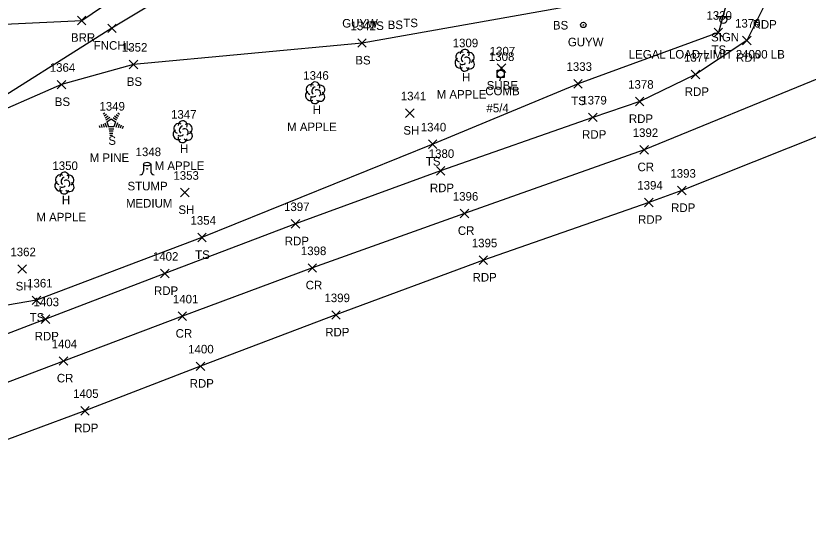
# Model space of a CAD drawing. Extents: x 1688195 to 1692013, y 424605 to 441234.
# Drawn here: x 1691718.1 to 1691903, y 439041.4 to 439158.5 of the extents above; entities that cross this region are included whole.
import ezdxf

# ---------------------------------------------------------------- set-up
doc = ezdxf.new("R2010")
doc.units = 0
for name, color, linetype in [('L_A', 7, 'Continuous'), ('L_C', 7, 'Continuous'), ('L_I', 7, 'Continuous'), ('L_TIC', 7, 'Continuous'), ('LABL', 7, 'Continuous'), ('LELB', 7, 'Continuous'), ('LFNC', 7, 'Continuous'), ('LTC', 7, 'Continuous'), ('LTD', 7, 'Continuous'), ('LTS', 7, 'Continuous'), ('P_A', 7, 'Continuous'), ('P_I', 7, 'Continuous'), ('P_TIC', 7, 'Continuous'), ('PET', 7, 'Continuous'), ('PRC', 7, 'Continuous'), ('S_A', 7, 'Continuous'), ('S_C', 7, 'Continuous'), ('SSGN', 7, 'Continuous'), ('U_A', 7, 'Continuous'), ('U_C', 7, 'Continuous'), ('U_I', 7, 'Continuous'), ('U_TIC', 7, 'Continuous'), ('UP', 7, 'Continuous'), ('UPGW', 7, 'Continuous')]:
    doc.layers.add(name, color=color, linetype=linetype)

msp = doc.modelspace()

# ---------------------------------------------------------------- linework, layer by layer
at = {"layer": 'L_TIC'}
for points in [[(1691732.43, 439156.4), (1691734.43, 439158.4)], [(1691734.43, 439156.4), (1691732.43, 439158.4)], [(1691739.49, 439154.55), (1691741.49, 439156.55)], [(1691741.49, 439154.55), (1691739.49, 439156.55)], [(1691881, 439153.55), (1691883, 439155.55)], [(1691883, 439153.55), (1691881, 439155.55)], [(1691797.84, 439151.11), (1691799.84, 439153.11)], [(1691799.84, 439151.11), (1691797.84, 439153.11)], [(1691744.51, 439146.11), (1691746.51, 439148.11)], [(1691746.51, 439146.11), (1691744.51, 439148.11)], [(1691727.71, 439141.4), (1691729.71, 439143.4)], [(1691729.71, 439141.4), (1691727.71, 439143.4)], [(1691848.25, 439141.61), (1691850.25, 439143.61)], [(1691850.25, 439141.61), (1691848.25, 439143.61)], [(1691809.01, 439134.72), (1691811.01, 439136.72)], [(1691811.01, 439134.72), (1691809.01, 439136.72)], [(1691814.33, 439127.47), (1691816.33, 439129.47)], [(1691816.33, 439127.47), (1691814.33, 439129.47)], [(1691756.51, 439116.18), (1691758.51, 439118.18)], [(1691758.51, 439116.18), (1691756.51, 439118.18)], [(1691760.5, 439105.68), (1691762.5, 439107.68)], [(1691762.5, 439105.68), (1691760.5, 439107.68)], [(1691718.52, 439098.33), (1691720.52, 439100.33)], [(1691720.52, 439098.33), (1691718.52, 439100.33)], [(1691721.87, 439091.03), (1691723.87, 439093.03)], [(1691723.87, 439091.03), (1691721.87, 439093.03)]]:
    msp.add_lwpolyline(points, dxfattribs=at)
at = {"layer": 'LABL'}
msp.add_lwpolyline([(1691601.59, 439075.8), (1691600.49, 439085.06), (1691627.74, 439119.17), (1691640.71, 439127.56), (1691655.14, 439108.61), (1691685.11, 439134.92), (1691687.62, 439141.73), (1691698.9, 439155.76), (1691733.43, 439157.4), (1691776.41, 439186.57), (1691794.38, 439190.21)], dxfattribs=at)
at = {"layer": 'LELB'}
for points in [[(1691809.05, 439198.7), (1691810.07, 439220.42), (1691810.47, 439227.71), (1691810.04, 439233.75), (1691820.98, 439231.16), (1691837.25, 439226.41), (1691844.55, 439222.68), (1691860.67, 439213.28), (1691879.41, 439197.19), (1691884.86, 439187.77), (1691888.44, 439178.13), (1691882, 439154.55), (1691849.25, 439142.61), (1691815.33, 439128.47), (1691761.5, 439106.68), (1691722.87, 439092.03), (1691697.52, 439087.73), (1691657.95, 439070.39), (1691613.62, 439049.58), (1691576.98, 439020.14), (1691544.83, 438993.15), (1691508.2, 438954.88), (1691488.69, 438935.2)], [(1691867.08, 439165.21), (1691844.95, 439160.27), (1691798.84, 439152.11), (1691745.51, 439147.11), (1691728.71, 439142.4), (1691709.09, 439133.88), (1691683, 439117.2), (1691643.28, 439091.08), (1691604.89, 439061.29), (1691572.53, 439026.72), (1691542.38, 438995.55), (1691505.84, 438957.5), (1691487.66, 438936.34), (1691466.81, 438915.54), (1691436.02, 438880.86), (1691415.55, 438858.76)]]:
    msp.add_lwpolyline(points, dxfattribs=at)
at = {"layer": 'LFNC'}
msp.add_lwpolyline([(1691844.63, 439219.19), (1691827.3, 439208.18), (1691808.98, 439197.07), (1691805.18, 439194.78), (1691802.65, 439193.15), (1691780.93, 439179.95), (1691740.49, 439155.55), (1691707.63, 439134.9), (1691682.09, 439120.04), (1691638.96, 439093.47), (1691599.84, 439067.34), (1691566.38, 439033.38), (1691536.95, 439001.22), (1691500.89, 438961.26), (1691462.91, 438919.55), (1691429.39, 438883.14), (1691411.26, 438863.12)], dxfattribs=at)
at = {"layer": 'LTC'}
for p, q in [((1691738.46, 439135.55), (1691738.82, 439135.81)), ((1691738.67, 439135.09), (1691739.2, 439135.47)), ((1691738.88, 439134.62), (1691739.58, 439135.13)), ((1691739.09, 439134.15), (1691739.97, 439134.79)), ((1691740.75, 439134.75), (1691741.56, 439134.16)), ((1691741.12, 439135.09), (1691741.8, 439134.6)), ((1691741.49, 439135.44), (1691742.04, 439135.04)), ((1691741.86, 439135.79), (1691742.28, 439135.49)), ((1691737.49, 439132.83), (1691737.65, 439132.36)), ((1691737.95, 439133.05), (1691738.16, 439132.39)), ((1691738.4, 439133.26), (1691738.68, 439132.43)), ((1691738.86, 439133.48), (1691739.19, 439132.46)), ((1691739.31, 439133.7), (1691740.33, 439134.43)), ((1691739.31, 439133.7), (1691739.7, 439132.51)), ((1691740.33, 439134.43), (1691741.32, 439133.71)), ((1691741.32, 439133.71), (1691740.93, 439132.51)), ((1691741.76, 439133.44), (1691741.42, 439132.4)), ((1691742.2, 439133.19), (1691741.92, 439132.3)), ((1691742.65, 439132.94), (1691742.41, 439132.21)), ((1691740.93, 439132.51), (1691739.7, 439132.51)), ((1691740.89, 439132.01), (1691739.75, 439132.01)), ((1691740.81, 439131.51), (1691739.82, 439131.51)), ((1691740.73, 439131.01), (1691739.89, 439131.01)), ((1691743.09, 439132.69), (1691742.91, 439132.11)), ((1691740.64, 439130.51), (1691739.97, 439130.51))]:
    msp.add_line(p, q, dxfattribs=at)
at = {"layer": 'LTD'}
for p, q in [((1691822.78, 439148.13), (1691822.78, 439148.13)), ((1691822.78, 439148.13), (1691822.78, 439148.13)), ((1691787.88, 439140.54), (1691787.88, 439140.54)), ((1691787.88, 439140.54), (1691787.88, 439140.54)), ((1691756.97, 439131.45), (1691756.97, 439131.45)), ((1691756.97, 439131.45), (1691756.97, 439131.45)), ((1691729.37, 439119.46), (1691729.37, 439119.46)), ((1691729.37, 439119.46), (1691729.37, 439119.46))]:
    msp.add_line(p, q, dxfattribs=at)
for centre in [(1691822.82, 439149.57), (1691787.93, 439141.97), (1691757.02, 439132.88), (1691729.41, 439120.9)]:
    msp.add_arc(centre, 1.05, 335.5272, 180.9563, dxfattribs=at)
for centre, major_axis, ratio, start_param, end_param in [((1691821.99, 439148.8), (1.21, -0.51), 0.895232, 1.570796, 4.712389), ((1691822.57, 439148.59), (-0.208, -0.792), 0.645439, 3.141593, 6.283185), ((1691823.82, 439148.72), (-1.14, -0.48), 0.949671, 1.570796, 4.712389), ((1691821.69, 439147.43), (0.58, -1.04), 0.959034, 3.141593, 6.283185), ((1691823.28, 439147.97), (-0.5, 0.667), 0.989748, 3.141593, 6.283185), ((1691823.78, 439147.3), (-1.09, 0.79), 0.841452, 1.570796, 4.712389), ((1691822.78, 439146.63), (0.26, 1.06), 0.942809, 1.570796, 4.712389), ((1691822.32, 439147.38), (-0.625, -0.083), 0.423636, 0, 3.141593), ((1691787.09, 439141.21), (1.21, -0.51), 0.895232, 1.570796, 4.712389), ((1691788.92, 439141.12), (-1.14, -0.48), 0.949671, 1.570796, 4.712389), ((1691786.8, 439139.83), (0.58, -1.04), 0.959034, 3.141593, 6.283185), ((1691787.67, 439141), (-0.208, -0.792), 0.645439, 3.141593, 6.283185), ((1691788.38, 439140.37), (-0.5, 0.667), 0.989748, 3.141593, 6.283185), ((1691788.88, 439139.71), (-1.09, 0.79), 0.841452, 1.570796, 4.712389), ((1691787.88, 439139.04), (0.26, 1.06), 0.942809, 1.570796, 4.712389), ((1691787.42, 439139.79), (-0.625, -0.083), 0.423636, 0, 3.141593), ((1691756.18, 439132.11), (1.21, -0.51), 0.895232, 1.570796, 4.712389), ((1691756.76, 439131.91), (-0.208, -0.792), 0.645439, 3.141593, 6.283185), ((1691758.01, 439132.03), (-1.14, -0.48), 0.949671, 1.570796, 4.712389), ((1691755.89, 439130.74), (0.58, -1.04), 0.959034, 3.141593, 6.283185), ((1691757.47, 439131.28), (-0.5, 0.667), 0.989748, 3.141593, 6.283185), ((1691757.97, 439130.62), (-1.09, 0.79), 0.841452, 1.570796, 4.712389), ((1691756.97, 439129.95), (0.26, 1.06), 0.942809, 1.570796, 4.712389), ((1691756.51, 439130.7), (-0.625, -0.083), 0.423636, 0, 3.141593), ((1691728.57, 439120.13), (1.21, -0.51), 0.895232, 1.570796, 4.712389), ((1691729.16, 439119.92), (-0.208, -0.792), 0.645439, 3.141593, 6.283185), ((1691729.87, 439119.3), (-0.5, 0.667), 0.989748, 3.141593, 6.283185), ((1691730.41, 439120.05), (-1.14, -0.48), 0.949671, 1.570796, 4.712389), ((1691728.28, 439118.75), (0.58, -1.04), 0.959034, 3.141593, 6.283185), ((1691729.37, 439117.96), (0.26, 1.06), 0.942809, 1.570796, 4.712389), ((1691728.91, 439118.71), (-0.625, -0.083), 0.423636, 0, 3.141593), ((1691730.37, 439118.63), (-1.09, 0.79), 0.841452, 1.570796, 4.712389)]:
    msp.add_ellipse(centre, major_axis=major_axis, ratio=ratio, start_param=start_param, end_param=end_param, dxfattribs=at)
at = {"layer": 'LTS'}
for p, q in [((1691747.86, 439123.84), (1691747.86, 439122.18)), ((1691749.53, 439123.68), (1691749.53, 439123.84)), ((1691749.53, 439123.84), (1691749.53, 439122.18)), ((1691748.69, 439122.7), (1691748.69, 439122.7)), ((1691748.69, 439122.7), (1691748.69, 439122.7)), ((1691748.69, 439122.68), (1691748.69, 439122.68))]:
    msp.add_line(p, q, dxfattribs=at)
msp.add_circle((1691748.69, 439122.7), 0.0833, dxfattribs=at)
for centre, start, end in [((1691747.03, 439122.18), 270, 360), ((1691750.36, 439122.18), 180, 270)]:
    msp.add_arc(centre, 0.833, start, end, dxfattribs=at)
msp.add_ellipse((1691748.69, 439123.84), major_axis=(-0.833, 0), ratio=0.5, dxfattribs=at)
at = {"layer": 'P_TIC'}
for points in [[(1691887.63, 439151.73), (1691889.63, 439153.73)], [(1691889.63, 439151.73), (1691887.63, 439153.73)], [(1691875.67, 439143.76), (1691877.67, 439145.76)], [(1691877.67, 439143.76), (1691875.67, 439145.76)], [(1691862.64, 439137.44), (1691864.64, 439139.44)], [(1691864.64, 439137.44), (1691862.64, 439139.44)], [(1691851.71, 439133.76), (1691853.71, 439135.76)], [(1691853.71, 439133.76), (1691851.71, 439135.76)], [(1691863.7, 439126.18), (1691865.7, 439128.18)], [(1691865.7, 439126.18), (1691863.7, 439128.18)], [(1691816.19, 439121.28), (1691818.19, 439123.28)], [(1691818.19, 439121.28), (1691816.19, 439123.28)], [(1691872.49, 439116.66), (1691874.49, 439118.66)], [(1691874.49, 439116.66), (1691872.49, 439118.66)], [(1691864.77, 439113.89), (1691866.77, 439115.89)], [(1691866.77, 439113.89), (1691864.77, 439115.89)], [(1691821.78, 439111.3), (1691823.78, 439113.3)], [(1691823.78, 439111.3), (1691821.78, 439113.3)], [(1691782.33, 439108.87), (1691784.33, 439110.87)], [(1691784.33, 439108.87), (1691782.33, 439110.87)], [(1691826.16, 439100.41), (1691828.16, 439102.41)], [(1691828.16, 439100.41), (1691826.16, 439102.41)], [(1691786.26, 439098.58), (1691788.26, 439100.58)], [(1691788.26, 439098.58), (1691786.26, 439100.58)], [(1691751.81, 439097.27), (1691753.81, 439099.27)], [(1691753.81, 439097.27), (1691751.81, 439099.27)], [(1691723.96, 439086.65), (1691725.96, 439088.65)], [(1691725.96, 439086.65), (1691723.96, 439088.65)], [(1691755.92, 439087.3), (1691757.92, 439089.3)], [(1691757.92, 439087.3), (1691755.92, 439089.3)], [(1691791.77, 439087.6), (1691793.77, 439089.6)], [(1691793.77, 439087.6), (1691791.77, 439089.6)], [(1691728.19, 439076.85), (1691730.19, 439078.85)], [(1691730.19, 439076.85), (1691728.19, 439078.85)], [(1691760.14, 439075.62), (1691762.14, 439077.62)], [(1691762.14, 439075.62), (1691760.14, 439077.62)], [(1691733.19, 439065.23), (1691735.19, 439067.23)], [(1691735.19, 439065.23), (1691733.19, 439067.23)]]:
    msp.add_lwpolyline(points, dxfattribs=at)
at = {"layer": 'PET'}
for points in [[(1691892.5, 439160.46), (1691888.63, 439152.73), (1691876.67, 439144.76), (1691863.64, 439138.44), (1691852.71, 439134.76), (1691817.19, 439122.28), (1691783.33, 439109.87), (1691752.81, 439098.27), (1691724.96, 439087.65), (1691700.6, 439078.32)], [(1691962.88, 439130.56), (1691955.64, 439134.26), (1691948.02, 439136.72), (1691941.11, 439138.03), (1691934.22, 439138.24), (1691927.22, 439137.24), (1691921.33, 439135.77), (1691915.1, 439134.27), (1691873.49, 439117.66), (1691865.77, 439114.89), (1691827.16, 439101.41), (1691792.77, 439088.6), (1691761.14, 439076.62), (1691734.19, 439066.23), (1691708.14, 439056.57), (1691672.86, 439042.9), (1691649.54, 439032.89)]]:
    msp.add_lwpolyline(points, dxfattribs=at)
at = {"layer": 'PRC'}
msp.add_lwpolyline([(1691888.13, 439193.66), (1691921.53, 439164.99), (1691933.61, 439155.1), (1691905.33, 439143.8), (1691864.7, 439127.18), (1691822.78, 439112.3), (1691787.26, 439099.58), (1691756.92, 439088.3), (1691729.19, 439077.85), (1691704.03, 439068.3), (1691667.7, 439053.5), (1691645.71, 439043.49), (1691628.46, 439034.88), (1691608.73, 439022.92), (1691585.22, 439006.39), (1691574.92, 438998.75), (1691559.84, 438985.93), (1691543.5, 438970.76), (1691518.61, 438946.02), (1691478.27, 438903.21), (1691447.81, 438870), (1691426.94, 438847.45)], dxfattribs=at)
at = {"layer": 'SSGN'}
for p, q in [((1691881.51, 439158.34), (1691884.85, 439158.34)), ((1691883.16, 439157.51), (1691883.16, 439157.51))]:
    msp.add_line(p, q, dxfattribs=at)
msp.add_circle((1691883.16, 439157.51), 0.833, dxfattribs=at)
at = {"layer": 'U_TIC'}
for points in [[(1691830.4, 439145.22), (1691832.4, 439147.22)], [(1691832.4, 439145.22), (1691830.4, 439147.22)]]:
    msp.add_lwpolyline(points, dxfattribs=at)
at = {"layer": 'UP'}
for p, q in [((1691830.38, 439144.08), (1691830.38, 439145.75)), ((1691830.38, 439145.75), (1691832.05, 439145.75)), ((1691831.47, 439146.58), (1691831.22, 439145.75)), ((1691832.05, 439145.75), (1691832.05, 439144.08)), ((1691832.05, 439144.08), (1691830.38, 439144.08)), ((1691830.97, 439143.25), (1691831.22, 439144.08)), ((1691831.22, 439144.92), (1691831.22, 439144.92))]:
    msp.add_line(p, q, dxfattribs=at)
msp.add_circle((1691831.22, 439144.92), 0.833, dxfattribs=at)
at = {"layer": 'UPGW'}
for radius in [0.625, 0.0833]:
    msp.add_circle((1691850.49, 439156.34), radius, dxfattribs=at)

# ---------------------------------------------------------------- texts
at = {"layer": 'L_A'}
for s, p in [('TS', (1691800.52, 439155.16)), ('BS', (1691804.83, 439155.37)), ('TS', (1691808.48, 439155.82)), ('BS', (1691843.39, 439155.27)), ('BRR', (1691730.92, 439152.4)), ('FNCHL', (1691736.24, 439150.55)), ('TS', (1691880.41, 439149.55)), ('BS', (1691797.28, 439147.11)), ('BS', (1691743.95, 439142.11)), ('H', (1691822.21, 439143.13)), ('BS', (1691727.15, 439137.4)), ('TS', (1691847.66, 439137.61)), ('H', (1691787.32, 439135.54)), ('SH', (1691808.5, 439130.72)), ('S', (1691739.65, 439128.34)), ('H', (1691756.4, 439126.45)), ('TS', (1691813.73, 439123.47)), ('STUMP', (1691744.12, 439117.7)), ('H', (1691728.8, 439114.46)), ('SH', (1691756, 439112.18)), ('TS', (1691759.91, 439101.68)), ('SH', (1691718.01, 439094.33)), ('TS', (1691721.28, 439087.03))]:
    msp.add_text(s, height=2, dxfattribs=at).set_placement(p)
at = {"layer": 'L_C'}
for s, p in [('M APPLE', (1691816.26, 439139.13)), ('M APPLE', (1691781.36, 439131.54)), ('M PINE', (1691735.29, 439124.34)), ('M APPLE', (1691750.45, 439122.45)), ('MEDIUM', (1691743.75, 439113.7)), ('M APPLE', (1691722.85, 439110.46))]:
    msp.add_text(s, height=2, dxfattribs=at).set_placement(p)
at = {"layer": 'L_I'}
for s, p in [('1330', (1691879.22, 439157.55)), ('1342', (1691796.14, 439155.11)), ('1309', (1691820, 439151.13)), ('1352', (1691742.81, 439150.11)), ('1333', (1691846.56, 439145.61)), ('1364', (1691725.97, 439145.4)), ('1346', (1691785.13, 439143.54)), ('1341', (1691807.89, 439138.72)), ('1349', (1691737.56, 439136.34)), ('1347', (1691754.28, 439134.45)), ('1340', (1691812.55, 439131.47)), ('1348', (1691746, 439125.7)), ('1350', (1691726.59, 439122.46)), ('1353', (1691754.82, 439120.18)), ('1354', (1691758.81, 439109.68)), ('1362', (1691716.78, 439102.33)), ('1361', (1691720.69, 439095.03))]:
    msp.add_text(s, height=2, dxfattribs=at).set_placement(p)
at = {"layer": 'LTC'}
msp.add_text('.', height=1.04, rotation=270, dxfattribs=at).set_placement((1691740.21, 439133.45))
at = {"layer": 'P_A'}
for s, p in [('RDP', (1691889.99, 439155.46)), ('RDP', (1691886.12, 439147.73)), ('RDP', (1691874.16, 439139.76)), ('RDP', (1691861.12, 439133.44)), ('RDP', (1691850.2, 439129.76)), ('CR', (1691863.13, 439122.18)), ('RDP', (1691814.68, 439117.28)), ('RDP', (1691870.98, 439112.66)), ('RDP', (1691863.26, 439109.89)), ('CR', (1691821.21, 439107.3)), ('RDP', (1691780.82, 439104.87)), ('RDP', (1691824.64, 439096.41)), ('CR', (1691785.7, 439094.58)), ('RDP', (1691750.3, 439093.27)), ('CR', (1691755.35, 439083.3)), ('RDP', (1691790.26, 439083.6)), ('RDP', (1691722.45, 439082.65)), ('CR', (1691727.63, 439072.85)), ('RDP', (1691758.62, 439071.62)), ('RDP', (1691731.68, 439061.23))]:
    msp.add_text(s, height=2, dxfattribs=at).set_placement(p)
at = {"layer": 'P_I'}
for s, p in [('1376', (1691885.89, 439155.73)), ('1377', (1691873.98, 439147.76)), ('1378', (1691860.94, 439141.44)), ('1379', (1691850.01, 439137.76)), ('1392', (1691862.01, 439130.18)), ('1380', (1691814.41, 439125.28)), ('1393', (1691870.8, 439120.66)), ('1394', (1691863.08, 439117.89)), ('1396', (1691820.03, 439115.3)), ('1397', (1691780.64, 439112.87)), ('1395', (1691824.46, 439104.41)), ('1402', (1691750.04, 439101.27)), ('1398', (1691784.57, 439102.58)), ('1403', (1691722.19, 439090.65)), ('1401', (1691754.71, 439091.3)), ('1399', (1691790.07, 439091.6)), ('1404', (1691726.42, 439080.85)), ('1400', (1691758.28, 439079.62)), ('1405', (1691731.42, 439069.23))]:
    msp.add_text(s, height=2, dxfattribs=at).set_placement(p)
at = {"layer": 'S_A'}
msp.add_text('SIGN', height=2, dxfattribs=at).set_placement((1691880.3, 439152.49))
at = {"layer": 'S_C'}
msp.add_text('LEGAL LOAD LIMIT 24000 LB', height=2, dxfattribs=at).set_placement((1691861.09, 439148.49))
at = {"layer": 'U_A'}
for s, p in [('GUYW', (1691794.22, 439155.73)), ('GUYW', (1691846.88, 439151.34)), ('SUBE', (1691827.94, 439141.22)), ('COMB', (1691827.6, 439139.92))]:
    msp.add_text(s, height=2, dxfattribs=at).set_placement(p)
at = {"layer": 'U_C'}
msp.add_text('#5/4', height=2, dxfattribs=at).set_placement((1691827.88, 439135.92))
at = {"layer": 'U_I'}
for s, p in [('1308', (1691828.45, 439147.92)), ('1307', (1691828.63, 439149.22))]:
    msp.add_text(s, height=2, dxfattribs=at).set_placement(p)

doc.saveas('drawing.dxf')
